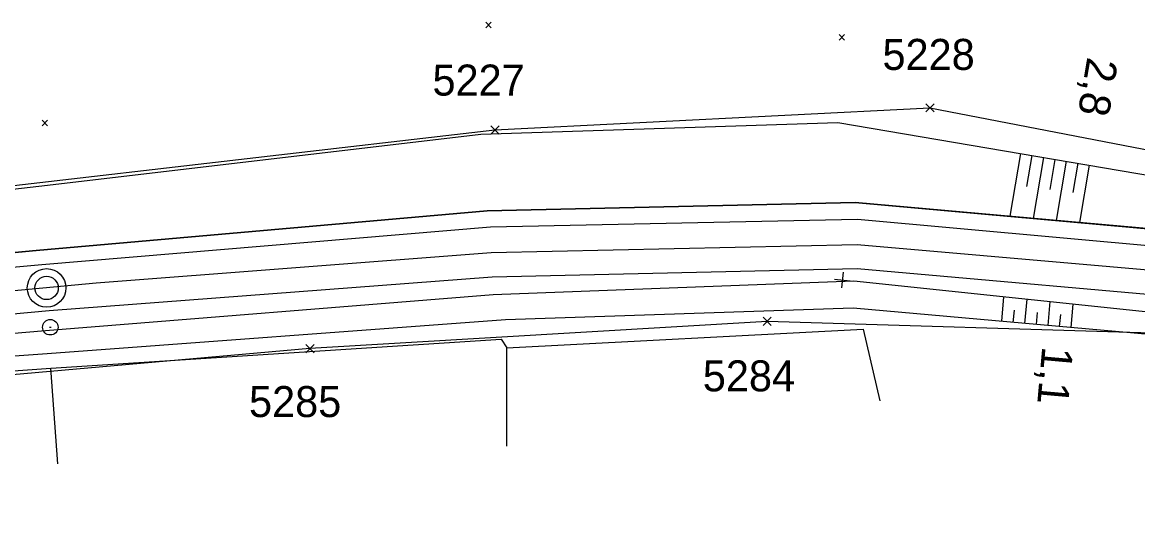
# Model space of a CAD drawing. Extents: x -805636 to -804553, y -1165340 to -1164656.
# Drawn here: x -805491.5 to -805419.6, y -1164900.4 to -1164867.2 of the extents above; entities that cross this region are included whole.
import ezdxf

# ---------------------------------------------------------------- set-up
doc = ezdxf.new("R2010")
doc.units = 0
for name, color, linetype in [('0381KM061-064P - Vrstva 1', 7, 'Continuous'), ('0381KM061-064P - Vrstva 17', 7, 'Continuous'), ('0381KM061-064P - Vrstva 4', 7, 'Continuous'), ('0381KM061-064P - Vrstva 48', 7, 'Continuous'), ('0381KM061-064P - Vrstva 49', 7, 'Continuous'), ('0381KM061-064P - Vrstva 7', 7, 'Continuous'), ('szdc - hran DP', 7, 'Continuous'), ('szdc - szdc_cislo', 7, 'Continuous'), ('szdc - szdc_krizek', 7, 'Continuous')]:
    doc.layers.add(name, color=color, linetype=linetype)

msp = doc.modelspace()

# ---------------------------------------------------------------- linework, layer by layer
at = {"layer": '0381KM061-064P - Vrstva 1'}
msp.add_lwpolyline([(-805621.704, -1164896.484), (-805615.585, -1164895.981), (-805590.014, -1164893.62), (-805528.478, -1164887.901), (-805486.763, -1164883.981), (-805461.299, -1164882.035), (-805437.692, -1164881.512), (-805413.273, -1164883.656)], dxfattribs=at)
at = {"layer": '0381KM061-064P - Vrstva 17'}
for p, q in [((-805460.286, -1164894.521), (-805460.285, -1164888.193)), ((-805489.25, -1164895.675), (-805489.686, -1164889.492))]:
    msp.add_line(p, q, dxfattribs=at)
msp.add_lwpolyline([(-805536.864, -1164897.857), (-805537.373, -1164893.168), (-805513.535, -1164891.185), (-805489.686, -1164889.492), (-805460.65, -1164887.615), (-805460.285, -1164888.193), (-805437.317, -1164886.987), (-805436.248, -1164891.591)], dxfattribs=at)
at = {"layer": '0381KM061-064P - Vrstva 4'}
for p, q in [((-805461.56, -1164879.343), (-805437.823, -1164878.806)), ((-805437.823, -1164878.806), (-805412.781, -1164881.052)), ((-805490.633, -1164881.901), (-805461.56, -1164879.343)), ((-805461.346, -1164880.404), (-805490.281, -1164882.825)), ((-805437.678, -1164879.902), (-805461.346, -1164880.404)), ((-805412.96, -1164882.157), (-805437.678, -1164879.902)), ((-805528.628, -1164885.468), (-805490.633, -1164881.901)), ((-805490.281, -1164882.825), (-805528.618, -1164886.229))]:
    msp.add_line(p, q, dxfattribs=at)
for points in [[(-805383.815, -1164892.413), (-805391.138, -1164890.05), (-805413.398, -1164885.24), (-805437.693, -1164883.083), (-805461.239, -1164883.617), (-805489.811, -1164885.789), (-805528.465, -1164889.37), (-805589.939, -1164894.996), (-805615.477, -1164897.548), (-805622.384, -1164898.082)], [(-805622.831, -1164899.132), (-805615.585, -1164898.49), (-805589.92, -1164896.02), (-805528.493, -1164890.341), (-805490.028, -1164887.057), (-805461.175, -1164884.746), (-805437.909, -1164883.87), (-805413.614, -1164886.429), (-805397.335, -1164889.692), (-805391.357, -1164890.969), (-805383.815, -1164892.413)]]:
    msp.add_lwpolyline(points, dxfattribs=at)
at = {"layer": '0381KM061-064P - Vrstva 48'}
for p, q in [((-805427.176, -1164875.651), (-805427.862, -1164879.699)), ((-805426.437, -1164875.776), (-805426.775, -1164877.771)), ((-805425.697, -1164875.902), (-805426.364, -1164879.834)), ((-805424.958, -1164876.027), (-805425.286, -1164877.964)), ((-805424.218, -1164876.152), (-805424.865, -1164879.968)), ((-805423.479, -1164876.277), (-805423.797, -1164878.156)), ((-805422.739, -1164876.403), (-805423.366, -1164880.103)), ((-805428.382, -1164886.472), (-805428.241, -1164884.888)), ((-805426.888, -1164886.606), (-805426.749, -1164885.045)), ((-805425.394, -1164886.739), (-805425.257, -1164885.203)), ((-805423.9, -1164886.872), (-805423.765, -1164885.36)), ((-805427.635, -1164886.539), (-805427.565, -1164885.753)), ((-805426.141, -1164886.672), (-805426.072, -1164885.898)), ((-805424.647, -1164886.805), (-805424.579, -1164886.043))]:
    msp.add_line(p, q, dxfattribs=at)
at = {"layer": '0381KM061-064P - Vrstva 49'}
for p, q in [((-805461.301, -1164867.538), (-805461.655, -1164867.184)), ((-805461.301, -1164867.184), (-805461.655, -1164867.538)), ((-805438.515, -1164868.333), (-805438.869, -1164867.979)), ((-805438.515, -1164867.979), (-805438.869, -1164868.333)), ((-805489.9, -1164873.861), (-805490.254, -1164873.507)), ((-805489.9, -1164873.507), (-805490.254, -1164873.861))]:
    msp.add_line(p, q, dxfattribs=at)
for points in [[(-805619.348, -1164890.946), (-805615.907, -1164890.53), (-805590.563, -1164886.386), (-805529.034, -1164882.212), (-805489.902, -1164877.68), (-805461.977, -1164874.39), (-805438.957, -1164873.655), (-805412.144, -1164878.198), (-805389.289, -1164884.476), (-805375.598, -1164889.137)], [(-805379.556, -1164889.142), (-805389.788, -1164885.886), (-805412.781, -1164881.052), (-805437.823, -1164878.806), (-805461.56, -1164879.343), (-805490.633, -1164881.901), (-805528.628, -1164885.468), (-805589.685, -1164890.913), (-805616.183, -1164893.177), (-805620.48, -1164893.608)], [(-805622.831, -1164899.132), (-805615.585, -1164898.49), (-805589.92, -1164896.02), (-805528.493, -1164890.341), (-805490.028, -1164887.057), (-805461.175, -1164884.746), (-805437.909, -1164883.87), (-805413.614, -1164886.429), (-805397.335, -1164889.692), (-805394.785, -1164892.277)], [(-805394.785, -1164892.277), (-805397.926, -1164890.9), (-805413.803, -1164887.771), (-805437.965, -1164885.619), (-805460.375, -1164886.37), (-805489.928, -1164888.57), (-805513.347, -1164890.238), (-805537.397, -1164892.439), (-805590.643, -1164897.221), (-805615.625, -1164899.613), (-805623.383, -1164900.43)]]:
    msp.add_lwpolyline(points, dxfattribs=at)
at = {"layer": '0381KM061-064P - Vrstva 7'}
for p, q in [((-805438.615, -1164883.309), (-805438.703, -1164884.305)), ((-805439.157, -1164883.763), (-805438.161, -1164883.851)), ((-805489.777, -1164886.859), (-805489.677, -1164886.851))]:
    msp.add_line(p, q, dxfattribs=at)
for centre, radius in [((-805489.965, -1164884.321), 1.246), ((-805489.965, -1164884.321), 0.752), ((-805489.727, -1164886.855), 0.5)]:
    msp.add_circle(centre, radius, dxfattribs=at)
at = {"layer": 'szdc - hran DP'}
for p, q in [((-805461.06, -1164874.13), (-805433.01, -1164872.7)), ((-805433.01, -1164872.7), (-805414.192, -1164876.333)), ((-805493.019, -1164877.826), (-805461.06, -1164874.13)), ((-805443.504, -1164886.48), (-805472.984, -1164888.236)), ((-805412.47, -1164887.438), (-805443.504, -1164886.48)), ((-805472.984, -1164888.236), (-805537.37, -1164893.92))]:
    msp.add_line(p, q, dxfattribs=at)
at = {"layer": 'szdc - szdc_krizek'}
for p, q in [((-805432.745, -1164872.965), (-805433.276, -1164872.435)), ((-805433.276, -1164872.965), (-805432.745, -1164872.435)), ((-805460.795, -1164874.395), (-805461.326, -1164873.865)), ((-805461.326, -1164874.395), (-805460.795, -1164873.865)), ((-805443.239, -1164886.745), (-805443.77, -1164886.215)), ((-805443.77, -1164886.745), (-805443.239, -1164886.215)), ((-805472.719, -1164888.501), (-805473.25, -1164887.971)), ((-805473.25, -1164888.501), (-805472.719, -1164887.971))]:
    msp.add_line(p, q, dxfattribs=at)

# ---------------------------------------------------------------- texts
at = {"layer": '0381KM061-064P - Vrstva 48'}
for s, rotation, p in [('2,8', 260.38355, (-805422.851, -1164869.376)), ('1,1', 264.91035, (-805425.762, -1164888.058))]:
    msp.add_text(s, height=2, rotation=rotation, dxfattribs=at).set_placement(p)
at = {"layer": 'szdc - szdc_cislo'}
for s, p in [('5228', (-805436.07, -1164870.256)), ('5227', (-805465.085, -1164871.911)), ('5284', (-805447.656, -1164890.989)), ('5285', (-805476.915, -1164892.649))]:
    msp.add_text(s, height=2, dxfattribs=at).set_placement(p)

doc.saveas('drawing.dxf')
